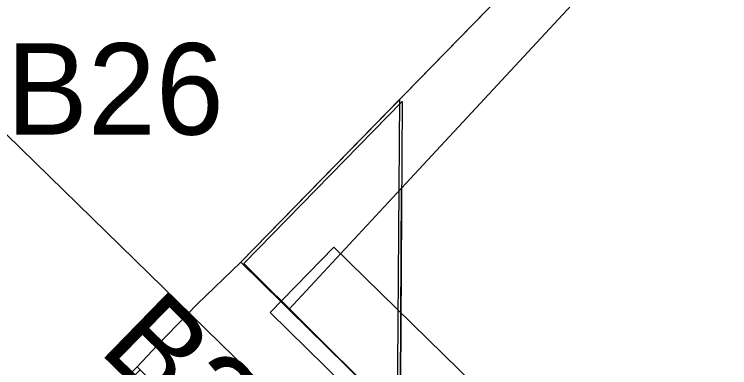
# Model space of a CAD drawing. Extents: x 2253035 to 2279930, y 13774972 to 13793443.
# Drawn here: x 2255727.31 to 2255758.63, y 13791697.34 to 13791712.8 of the extents above; entities that cross this region are included whole.
import ezdxf

# ---------------------------------------------------------------- set-up
doc = ezdxf.new("R2010")
doc.units = 0
for name, color, linetype in [('E_Utility_ATT_Fiber', 7, 'Continuous'), ('E_Utility_Gas_Gas Line_GL_Description', 7, 'Continuous'), ('E_Utility_Gas_Gas Line_GL_Elevation', 7, 'Continuous'), ('E_Utility_Guy Anchor_GUY_point', 7, 'Continuous'), ('E_Utility_Water_Water Line_WL_Description', 7, 'Continuous'), ('E_Utility_Water_Water Line_WL_Elevation', 7, 'Continuous')]:
    doc.layers.add(name, color=color, linetype=linetype)

msp = doc.modelspace()

# ---------------------------------------------------------------- linework, layer by layer
at = {"layer": 'E_Utility_ATT_Fiber'}
for p, q in [((2255739.331, 13791699.888), (2255744.266, 13791705.197)), ((2255744.266, 13791705.197), (2255739.331, 13791699.888)), ((2255744.11, 13791679.786), (2255744.266, 13791705.197)), ((2255744.266, 13791705.197), (2255744.11, 13791679.786)), ((2255743.066, 13791696.221), (2255739.331, 13791699.888)), ((2255739.331, 13791699.888), (2255743.066, 13791696.221))]:
    msp.add_line(p, q, dxfattribs=at)
for points in [[(2255744.266, 13791705.197), (2255818.142, 13791784.677), (2255818.485, 13791785.033)], [(2255818.485, 13791785.033), (2255818.142, 13791784.677), (2255744.266, 13791705.197)]]:
    msp.add_lwpolyline(points, dxfattribs=at)
msp.add_lwpolyline([(2255732.688, 13791697.372), (2255738.561, 13791691.611), (2255743.066, 13791696.221), (2255737.22, 13791701.96), (2255735.318, 13791700.111), (2255734.45, 13791699.226), (2255733.572, 13791698.327)], close=True, dxfattribs=at)
at = {"layer": 'E_Utility_Gas_Gas Line_GL_Description'}
msp.add_line((2255726.964, 13791707.535), (2255740.49, 13791694.353), dxfattribs=at)
at = {"layer": 'E_Utility_Guy Anchor_GUY_point'}
for p, q in [((2255738.509, 13791699.747), (2255741.304, 13791702.609)), ((2255741.304, 13791702.609), (2255738.509, 13791699.747)), ((2255741.304, 13791702.609), (2255747.742, 13791696.321)), ((2255747.742, 13791696.321), (2255741.304, 13791702.609)), ((2255738.509, 13791699.747), (2255742.086, 13791696.254))]:
    msp.add_line(p, q, dxfattribs=at)
msp.add_lwpolyline([(2255743.973, 13791679.92), (2255744.181, 13791709.085), (2255737.22, 13791701.96), (2255743.066, 13791696.221), (2255738.561, 13791691.611), (2255732.688, 13791697.372), (2255686.09, 13791649.274), (2255653.848, 13791683.471), (2255639.338, 13791669.268), (2255679.276, 13791629.46), (2255687.183, 13791621.589), (2255646.313, 13791579.703), (2255631.16, 13791559.162), (2255672.147, 13791556.295), (2255774.988, 13791661.7), (2255784.864, 13791671.82)], close=True, dxfattribs=at)
at = {"layer": 'E_Utility_Water_Water Line_WL_Description'}
msp.add_lwpolyline([(2255639.338, 13791669.268), (2255653.789, 13791683.405), (2255685.974, 13791649.225), (2255732.824, 13791697.239), (2255738.561, 13791691.611), (2255743.066, 13791696.221), (2255737.364, 13791701.891), (2255744.289, 13791708.989), (2255744.17, 13791689.549), (2255703.672, 13791642.737), (2255697.782, 13791633.762), (2255677.566, 13791613.044), (2255684.453, 13791625.27)], close=True, dxfattribs=at)
at = {"layer": 'E_Utility_Water_Water Line_WL_Elevation'}
msp.add_lwpolyline([(2255552.689, 13792209.602), (2255414.64, 13792056.034), (2255343.686, 13791984.842), (2255605.986, 13791701.862), (2255609.849, 13791705.811), (2255620.437, 13791715.999), (2255687.164, 13791650.788), (2255732.688, 13791697.372), (2255738.561, 13791691.611), (2255743.066, 13791696.221), (2255737.22, 13791701.96), (2255882.437, 13791850.604), (2255952.199, 13791922.137), (2256017.054, 13791988.637), (2256050.985, 13792008.429), (2256083.268, 13792042.751), (2256102.42, 13792056.554), (2256121.517, 13792085.403), (2256170.832, 13792144.183)], dxfattribs=at)
msp.add_lwpolyline([(2255888.455, 13791833.539), (2255895.058, 13791863.545), (2255737.22, 13791701.96), (2255743.066, 13791696.221), (2255738.561, 13791691.611), (2255732.688, 13791697.372), (2255687.164, 13791650.788), (2255620.437, 13791715.999), (2255529.194, 13791619.159), (2255654.521, 13791602.427), (2255648.22, 13791595.967), (2255641.919, 13791570.188), (2255680.312, 13791564.668), (2255857.507, 13791746.266), (2255934.018, 13791825.549)], close=True, dxfattribs=at)

# ---------------------------------------------------------------- texts
at = {"layer": 'E_Utility_Gas_Gas Line_GL_Elevation'}
msp.add_text('B26', height=4, dxfattribs=at).set_placement((2255726.964, 13791707.535))
msp.add_text('B26', height=4, rotation=315.7385, dxfattribs=at).set_placement((2255730.935, 13791698.079))

doc.saveas('drawing.dxf')
